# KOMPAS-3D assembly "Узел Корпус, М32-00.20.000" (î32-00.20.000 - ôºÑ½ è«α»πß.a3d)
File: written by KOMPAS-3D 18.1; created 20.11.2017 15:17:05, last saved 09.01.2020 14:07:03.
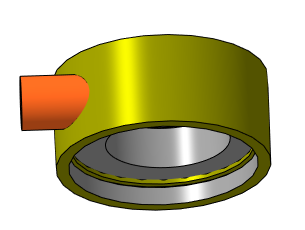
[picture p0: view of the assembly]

Document properties: Автор: Милов; Организация: Милов; Полное имя файла: D:\Magna\Магна Ins\Магна ins 32\Для Караби Магна 32\М32-00.20.000 - Узел Корпус.a3d

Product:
- Part/product: Узел Корпус  | designation М32-00.20.000  | pos. 0
    Материал: Полипропилен  ГОСТ 26996-86 (density 900 kg/m3)
    Масса: 3.02375
    Раздел спецификации: Сборочные единицы
    Форматы листов документа: A3
    source file: М32-00.20.000 - Корпус.cdw
  - Component [detail]: Корпус  | designation М32-00.20.002  | pos. 4  | Материал: Полипропилен  ГОСТ 26996-86 (density 900 kg/m3); Масса: 1.69089; Раздел спецификации: Детали; Форматы листов документа: A3; source file: М32-00.20.002 - Корпус.cdw, М32-00.20.002 - Корпус.m3d
  - Component [assembly]: Узел Кольцо  | designation М32-00.21.000  | pos. 1  | Масса: 1.29831; Раздел спецификации: Сборочные единицы; Форматы листов документа: A3; source file: М32-00.21.000 - Кольцо.cdw, М32-00.21.000 - Узел Кольцо.a3d, М32-00.21.000-01 - Кольцо.cdw
  - Component [detail]: Штифт 10  | designation М40-00.30.001  | pos. 10  | Масса: 0.0172762; Раздел спецификации: Детали; Форматы листов документа: A4; source file: М40-00.30.001 - Штифт 10.m3d
  - Component [detail]: Штифт 10  | designation М40-00.30.001  | pos. 9  | Масса: 0.0172762; Раздел спецификации: Детали; Форматы листов документа: A4; source file: М40-00.30.001 - Штифт 10.m3d

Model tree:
1. Смещенная плоскость:1  (with: Операция выдавливания:1)
     Расстояние = 39
2. Эскиз:2
3. Элемент выдавливания:2
     Расстояние 1 = 30; Расстояние 2 = 10
4. Массив по концентрической сетке:1  (with: Элемент выдавливания:2, Смещенная плоскость:1, Операция выдавливания:6)  (2 pattern instances)
     Шаг 2 = 360
5. Сечение поверхностью:2
6. Сечение поверхностью:1  (with: Операция выдавливания:6)  (labels: Полипропилен  ГОСТ 26996-86)

Referenced files in D:\Magna\Магна Ins\Магна ins 32\Для Караби Магна 32\: М32-00.21.000 - Узел Кольцо.a3d, М32-00.21.000-01 - Кольцо.cdw, М32-00.21.000 - Кольцо.cdw, М32-00.20.002 - Корпус.m3d, М32-00.20.002 - Корпус.cdw, М40-00.30.001 - Штифт 10.m3d
Referenced files in D:\Magna\Магна Ins\Магна ins 32\: М32-00.20.000 - Корпус.cdw
Referenced files in D:\Magna\Магна Ins\Магна ins 32\Для Караби\: М40-00.30.001 - Штифт 10.m3d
